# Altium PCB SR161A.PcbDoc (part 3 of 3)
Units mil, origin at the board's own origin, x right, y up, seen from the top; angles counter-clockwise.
Board outline 3150 x 3740 mil, 6 copper layers (Top Layer, Signal Layer 1, Signal Layer 2, Signal Layer 3, Signal Layer 4, Bottom Layer), stack 61.4 mil thick; 187 components, 70 nets, 452 pads, 384 vias.
Unrouted connection lines stored in the file: 5.
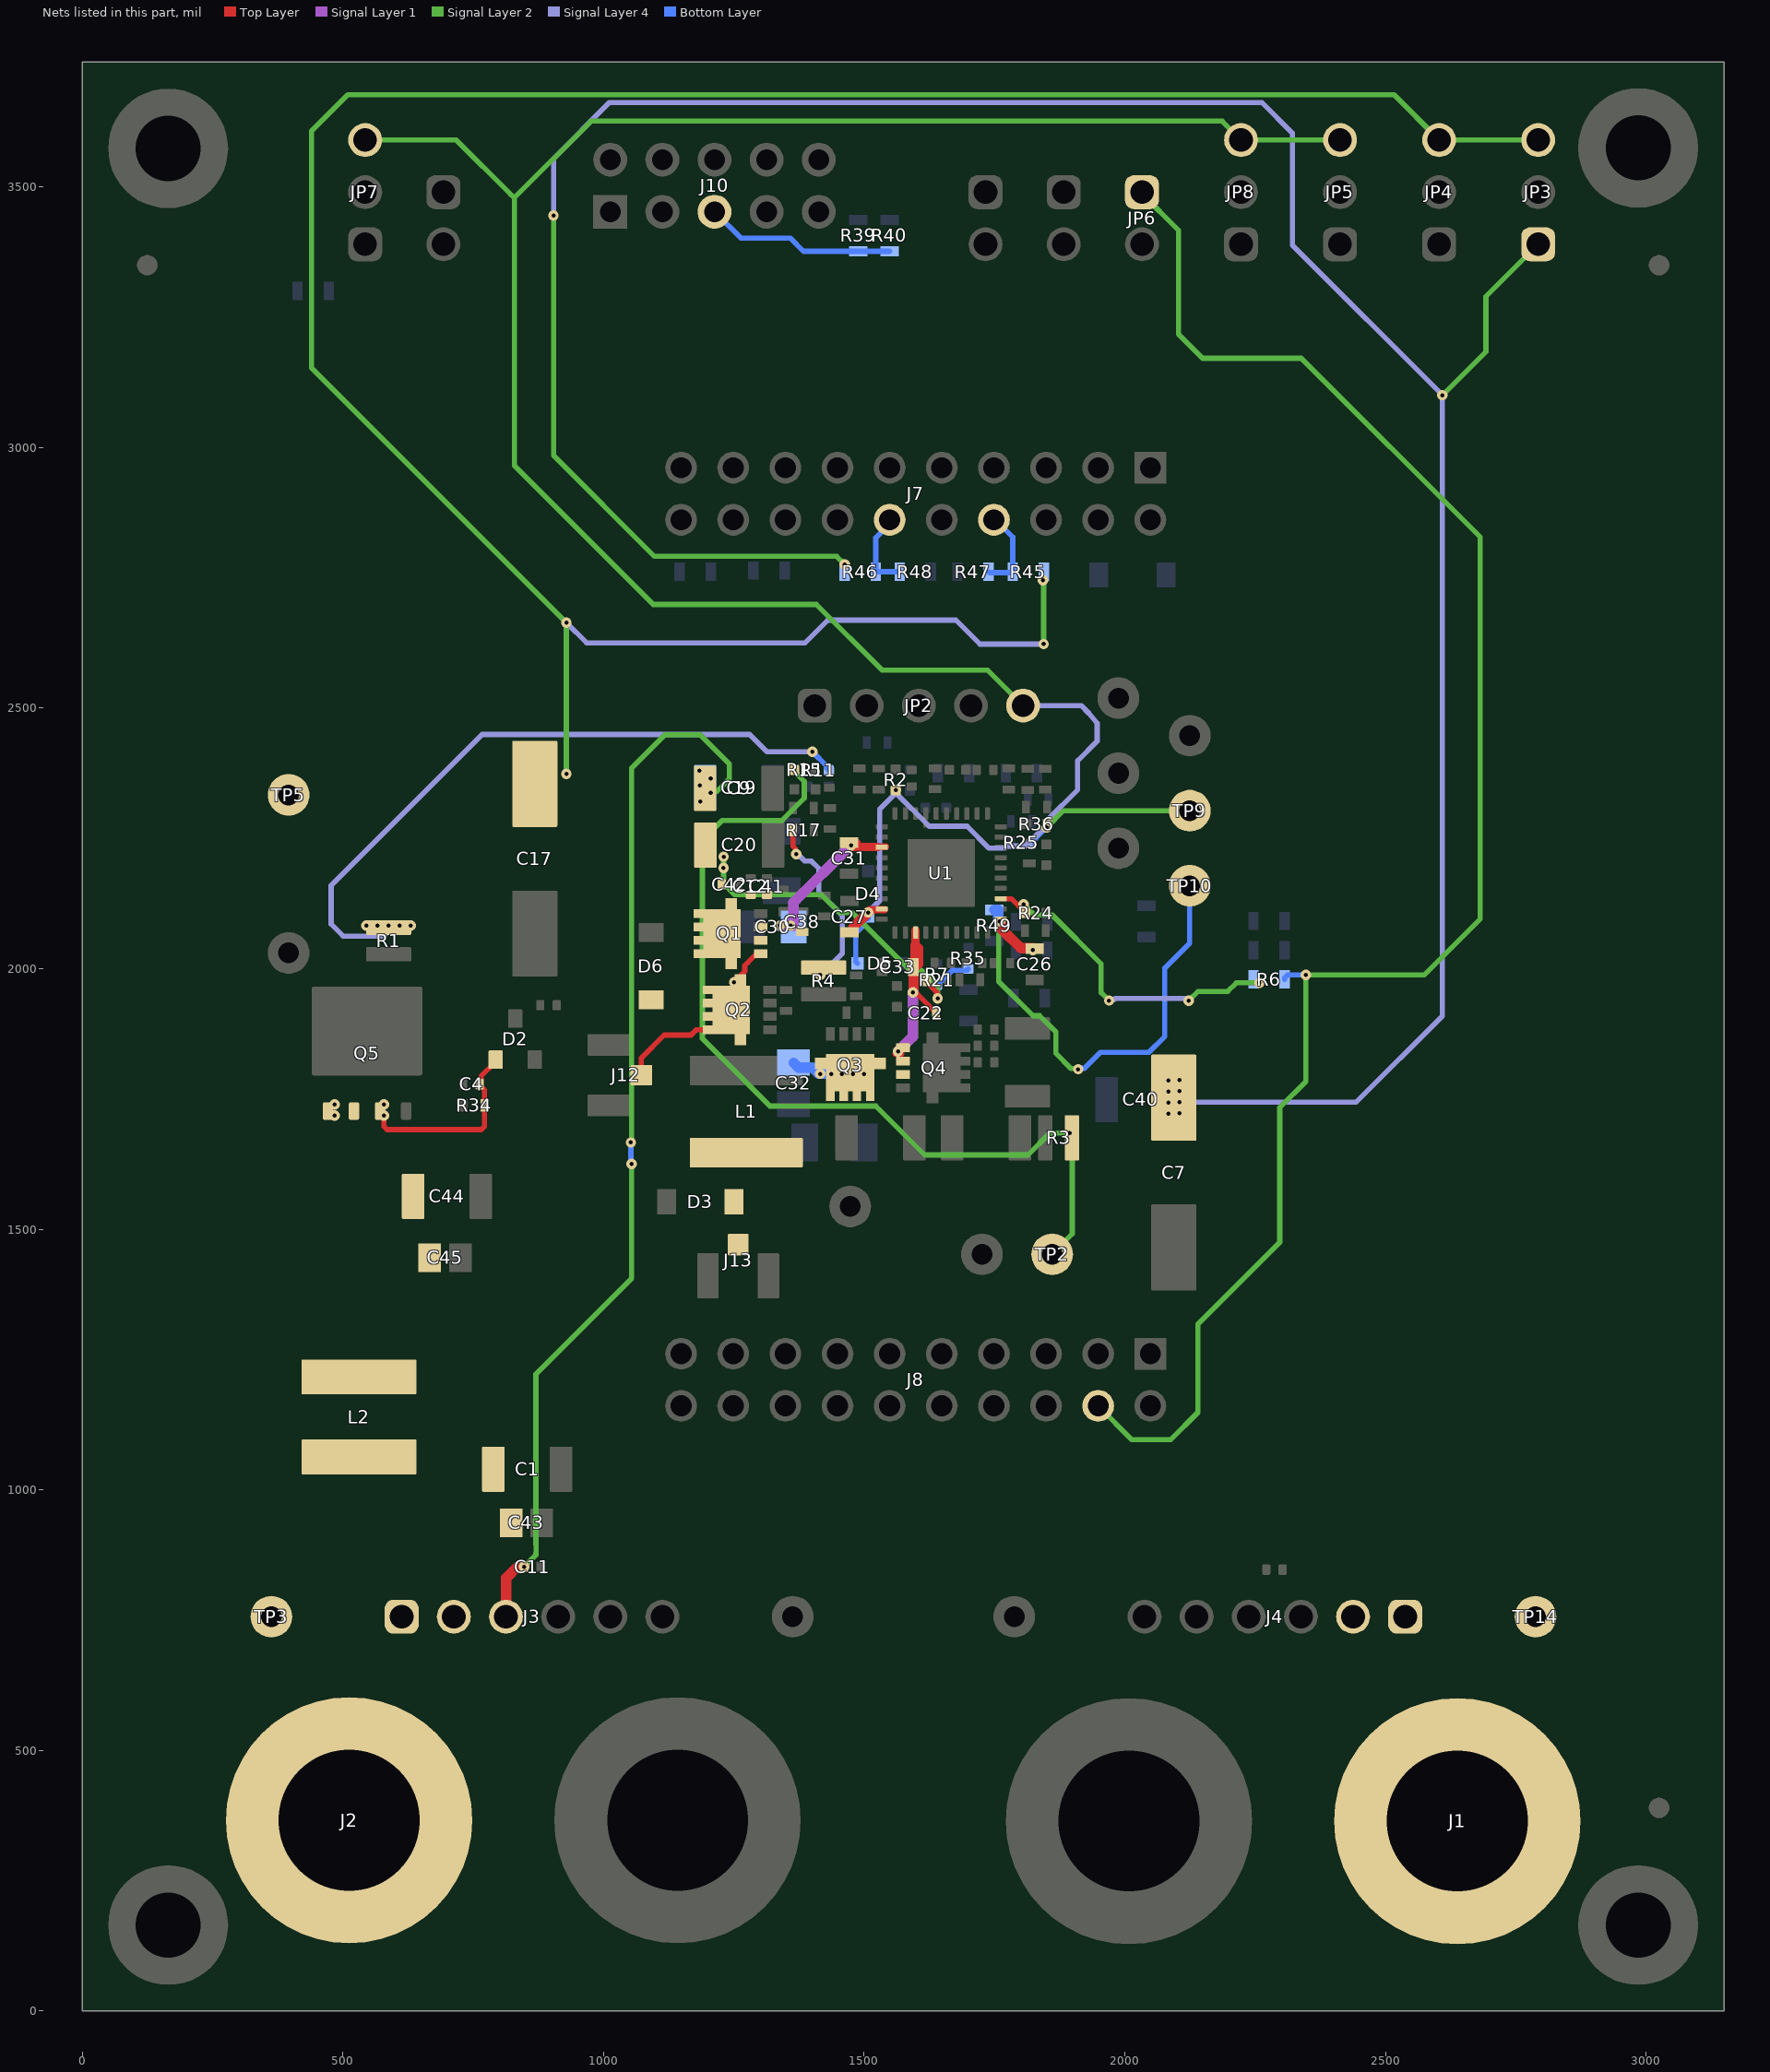
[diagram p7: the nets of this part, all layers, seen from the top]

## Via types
v1: diameter 20, hole 8, Top Layer to Bottom Layer, tented both sides, 366 vias
v2: diameter 19.68, hole 7.87, Top Layer to Bottom Layer, tented both sides, 12 vias
v3: diameter 24, hole 8, Top Layer to Bottom Layer, tented both sides, 6 vias

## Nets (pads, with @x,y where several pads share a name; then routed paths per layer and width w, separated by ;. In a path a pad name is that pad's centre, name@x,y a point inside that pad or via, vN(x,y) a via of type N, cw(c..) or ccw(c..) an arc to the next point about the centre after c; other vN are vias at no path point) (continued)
SW1: C30.2 C31.1 C38.2 D6.1 J12.1 Q1.1 Q1.2 Q1.3 Q2.5-6-7-8 R4.1 R17.2 U1.23 | length 908.5
  Top Layer w10: J12.1@1072.77,1795.91 1072.77,1828.89 1116.62,1872.74 1168.03,1872.74 1178.1,1882.81 Q2.5-6-7-8@1199.75,1882.81 ; Q2.5-6-7-8@1254.49,1979.13 1254.49,1982.31 Q2.5-6-7-8@1254.96,1982.31 ; Q2.5-6-7-8@1264.03,1987.93 1271.1,1995 1271.1,2006.16 1277.6,2012.66 1291.78,2026.83 1298.13,2026.83 Q1.1@1301.4,2030.1 ; R17.2@1363.57,2256 1363.57,2235.17 1367.87,2230.87 1367.87,2222.02 v1(1369.78,2220.1)
  Top Layer w14: U1.23@1530.02,2234.17 U1.23@1540.69,2234.17
  Top Layer w16: C31.1@1474.4,2241.16 1475.96,2239.6 C31.1@1479.84,2239.6 ; C31.1@1476.2,2233.44 U1.23@1526.2,2233.44 ; C31.1@1479.84,2240.29 C31.1@1485.76,2240.29
  Signal Layer 1 w20: v1(1337.85,2082.46) 1364.28,2082.46 1364.28,2126.88 1474.15,2236.75 v1(1475.22,2236.75)
  Signal Layer 4 w10: v1(1369.78,2220.1) 1372.49,2220.1 1385.98,2206.61 1398.72,2206.61 1413.4,2191.93 1413.4,2147.23 1458.24,2102.38 1458.24,2029.26 1416.91,1987.93 v1(1415.58,1987.93)
  Bottom Layer w20: v1(1337.85,2082.46) C30.2@1364.28,2082.46
  other v1: 1250.71,1973.89 1359,2082.46
SW2: C22.1 C32.1 C33.1 D3.1 J13.1 L1.2 Q3.5-6-7-8 Q4.1 Q4.2 Q4.3 U1.33 | length 518.9
  Top Layer w10: Q3.5-6-7-8@1413.06,1814.47 1413.06,1814.96 1418.79,1820.69 Q3.5-6-7-8@1419.28,1820.69 ; Q3.5-6-7-8@1473.44,1800.75 Q3.5-6-7-8@1484.07,1800.75 ; Q4.1@1562.03,1845.35 1562.03,1838.95 1559.57,1836.49 v1@1572.35,1836.49 ; v1(1593.43,1954.59) 1595.34,1952.68 1601.41,1952.68 1635.05,1919.04 C22.1@1635.05,1914.54
  Top Layer w16: U1.33@1598.79,2065.82 U1.33@1598.79,2069.58 U1.33@1598.79,2073.82 ; 1598.83,2052.43 U1.33@1598.83,2065.77
  Top Layer w20: C33.1@1594.47,2003.85 1594.47,1990.89 1594.87,1990.49 v1@1594.87,1960.24 ; C33.1@1594.87,2000.67 1603.78,2009.58 1603.78,2038.42 ; C33.1@1598.58,2005.37 1598.58,2045.37
  Signal Layer 1 w20: v1(1564.98,1841.28) 1593.43,1869.73 v1(1593.43,1954.59)
  Bottom Layer w20: C32.1@1364.78,1819.55 1374.13,1810.2 1401,1810.2 1412.87,1798.32 v1(1436.69,1798.32) v1(1457.8,1798.32) v1(1500.02,1798.32)
  other v1: 1415.58,1798.32 1478.91,1798.32
SYNC: R6.1 R24.1 U1.3 | length 637.3
  Top Layer w10: U1.3@1768.98,2134.46 1782.3,2134.46 1798.34,2118.43 1809.02,2118.43 1809.02,2107.39 R24.1@1809.28,2107.13
  Signal Layer 2 w10: v1(1806.02,2123.81) 1826.55,2103.27 1860.72,2103.27 1954.83,2009.16 1954.83,1954.09 v1(1969.99,1938.93) ; v1(2122.71,1938.79) 2140.54,1956.63 2197.56,1956.63 2213.96,1973.02 v1(2258.41,1973.02)
  Signal Layer 4 w10: v1(1969.99,1938.93) 1971.9,1940.85 1978.97,1940.85 1981.52,1943.39 2115.4,1943.39 2120,1938.79 v1(2122.71,1938.79)
SYNCP: J8.4 JP6.1 R6.2 | length 3361
  Signal Layer 2 w10: J8.4@1949.03,1161.43 1948.81,1161.43 2013.88,1096.35 2087.91,1096.35 2140.32,1148.76 2140.32,1317.92 2297.44,1475.04 2297.44,1733.87 2347.26,1783.69 v1(2347.26,1987.99) 2574.03,1987.99 2682,2095.96 2682,2827.94 2338.5,3171.44 2149.27,3171.44 2102.93,3217.77 2102.93,3417.11 JP6.1@2033.24,3486.8
  Bottom Layer w10: R6.2@2306.88,1979.63 2306.88,1982.99 2311.88,1987.99 v1(2347.26,1987.99)
VBUS: J10.5 R39.2 R40.2 | length 366.1
  Bottom Layer w10: J10.5@1213.82,3451.74 1263.82,3401.74 1358.82,3401.74 1383.82,3376.74 R39.2@1488.82,3376.74 R40.2@1548.82,3376.74
VCC1: C26.2 R49.1 TP10.1 U1.1 | length 979.6
  Top Layer w20: v1@1763.98,2084.74 1763.98,2075.72 1799.15,2040.55 1801.35,2040.55 1802.57,2039.33 C26.2@1824.98,2039.33
  Signal Layer 2 w10: v1@1758.26,2081.47 1758.26,1975.35 1823.83,1909.79 1836.65,1909.79 1868.02,1878.42 1868.02,1837.57 1896.86,1808.73 1909.23,1808.73 v1(1910.72,1807.24) ; v1@1758.27,2081.48 1758.27,2088.55 v1(1760.19,2090.47)
  Bottom Layer w10: v1(1910.72,1807.24) 1912.64,1809.16 1922.71,1809.16 1953.21,1839.66 2046.39,1839.66 2076.94,1870.21 2076.94,2001.58 2124.72,2049.36 TP10.1@2124.72,2159.28
  Bottom Layer w20: R49.1@1749.62,2113.15 1757.12,2113.15 1757.12,2093.53 v1(1760.19,2090.47)
  other v1: 1823.37,2035.91
VCC2: C27.2 D4.2 D5.2 JP2.5 JP5.3 JP7.3 JP8.3 R2.2 R25.2 R36.1 TP9.1 U1.29 | length 5183.4
  Top Layer w14: v1@1510.9,2113.09 U1.29@1538.9,2113.09
  Top Layer w20: C27.2@1479.37,2079.48 v1@1509.62,2109.73
  Signal Layer 2 w10: JP7.3@543,3590.37 717.7,3590.37 821.63,3486.44 829.03,3479.04 ; JP2.5@1804.78,2505.1 1736.72,2573.15 1534.4,2573.15 1408.59,2698.96 1095.7,2698.96 829.03,2965.63 829.03,3479.04 ; v1(1850.25,2270.96) 1882.57,2303.28 TP9.1@2124.72,2303.28 ; JP5.3@2413,3590.37 2223,3590.37 2186.98,3626.39 976.39,3626.39 829.03,3479.04
  Signal Layer 4 w10: v1(1507.82,2107.96) 1507.82,2108.4 1529.93,2130.52 1529.93,2306.12 1560.13,2336.32 v1@1560.13,2338.34 ; v1@1560.13,2343.88 1560.13,2342.68 v1@1560.13,2338.34 ; v1@1561.11,2339.97 v1(1561.11,2342.68) ; JP2.5@1805,2505 1916.43,2505 1931.6,2489.84 1944.74,2473.79 1947,2471.03 1947,2436.62 1909.62,2399.24 1909.62,2343.66 1851.95,2285.99 1851.95,2272.66 v1(1850.25,2270.96) 1847.55,2270.96 1842.55,2265.96 1839.89,2265.96 1809.46,2235.53 1774.19,2235.53 1770.16,2231.51 1739.35,2231.51 1697.44,2273.41 1625.06,2273.41 v1@1560.13,2338.34
  Bottom Layer w10: D5.2@1487.35,2010.13 1483.86,2013.62 1483.86,2068.34 1500.9,2085.38 1500.9,2093.78 1503.45,2096.34 D4.2@1507.42,2096.34 ; R25.2@1822.26,2243.16 1822.26,2246.81 1824.76,2249.31 1828.41,2249.31 v1@1852.34,2273.24
VIN: C1.2 C4.2 C43.1 C44.2 C45.1 D2.1 J2.1 J3.1 J3.2 L2.1 L2.2 Q5.1 Q5.2 Q5.3 R34.2 TP3.1 | length 363.3
  Top Layer w10: v1(579.12,1718.31) 579.12,1697.34 584.98,1691.49 765.71,1691.49 771.96,1697.74 R34.2@771.96,1737.49 771.96,1767.2 762.56,1776.6 C4.2@762.56,1778.57 765.43,1781.44 765.43,1793.77 793.32,1821.66 D2.1@793.32,1825.6
  other v1: 484.07,1718.31 484.07,1739.42 579.12,1739.42
VIN_36: C9.2 C11.1 C12.1 C17.2 C19.2 C20.2 C41.1 C42.1 J3.3 JP3.3 JP4.3 Q1.5-6-7-8 R1.2 R7.2 R11.2 R21.2 R35.2 R45.1 TP5.1 | length 9017.5
  Top Layer w10: R21.2@1620.03,1978.74 1620.03,1974.24 1639.11,1955.16 1639.11,1945.02 v1(1641.02,1943.11)
  Top Layer w20: J3.3@813.61,756.82 813.61,831.13 835.09,852.61 C11.1@847.79,852.61
  Signal Layer 2 w10: v1(847.93,852.61) 870.52,875.21 870.52,878.09 870.71,878.28 870.71,895.68 870.52,895.87 870.52,1222.01 1054.06,1405.55 v1(1054.06,1625.23) v1@1052.57,1626.72 ; v1(928.95,2374.05) v1(928.95,2664.16) 440,3153.11 440,3607.22 509.9,3677.12 2516.25,3677.12 2603,3590.37 JP3.3@2793,3590.37 ; v1(1052.57,1666.75) 1054.06,1668.23 1054.06,2385.2 1118.03,2449.17 1185.08,2449.17 1241.58,2392.67 1241.58,2364.45 1216.33,2339.2 1207.62,2339.2 v1(1205.71,2337.29) ; v1(1230.4,2193.48) 1230.4,2163.57 1251.8,2142.16 1418.03,2142.16 1452.31,2107.88 1476.79,2107.88 1587.45,1997.22 1609.85,1997.22 1641.09,1965.98 v1@1641.09,1939.77 ; v1@1230.55,2197.35 v1(1230.55,2215.07) ; v1(1843.27,2745.31) 1844.44,2744.14 v1(1844.44,2623.02)
  Signal Layer 4 w10: v1(587.95,2082.78) 586.04,2080.87 586.04,2070.74 578.08,2062.79 500.7,2062.79 477.77,2085.71 477.77,2159.75 767.5,2449.48 1280.59,2449.48 1313.72,2416.35 v1(1400.73,2416.35) ; v1(928.95,2664.16) 967.69,2625.42 1386.81,2625.42 1430.38,2668.98 1676.17,2668.98 1722.13,2623.02 v1(1844.44,2623.02)
  Bottom Layer w10: v1@1052.57,1626.72 v1(1052.57,1666.75) ; v1(1400.73,2416.35) 1427.85,2389.22 1427.85,2385.36 R11.2@1432.2,2381.01 ; v1(1641.02,1943.11) 1640.52,1943.6 1640.52,1964.57 1639.07,1966.03 1639.07,1967.1 1669.03,1997.06 1697.23,1997.06 R35.2@1700,1999.82
  other v1: 545.42,2082.78 566.68,2082.78 609.21,2082.78 630.48,2082.78 1185.82,2320.76 1184.66,2352.12 1205.71,2365.29 1184.29,2379.68
VIN_SENSE: J7.8 R45.2 R47.2 | length 159.9
  Bottom Layer w10: R47.2@1738.93,2761.65 1740.59,2759.99 1783.41,2759.99 R45.2@1785.07,2761.65 1785.07,2828.37 1753.05,2860.39 J7.8@1753.05,2860.71
VOUT: C7.2 C40.2 J1.1 J4.1 J4.2 JP3.1 R3.2 R15.2 R46.1 TP2.1 TP14.1 | length 7223.5
  Signal Layer 2 w10: v1@904.19,3445.44 904.19,2985.11 1098.03,2791.27 1447.4,2791.27 v1@1460.03,2778.64 ; v1@1363.81,2381.91 1363.81,2381.01 1385.4,2359.42 1385.4,2327.41 1342.7,2284.71 1335.86,2284.71 1335.73,2284.58 1228.11,2284.58 1189.84,2246.31 1189.84,1866.1 1319.39,1736.55 1522.58,1736.55 1616.41,1642.71 1814.24,1642.71 1856.27,1684.74 v1(1894.08,1684.74) ; TP2.1@1860.73,1452.1 1860.73,1452.81 1899.26,1491.35 1899.26,1676.85 1894.22,1681.88 v1@1894.22,1684.59 ; v1(2609.35,3100.49) 2692.81,3183.95 2692.81,3289.81 JP3.1@2793,3390
  Signal Layer 4 w10: v1@904.19,3445.44 904.19,3554.7 1011.55,3662.07 2263.15,3662.07 2321.81,3603.41 2321.81,3388.03 v1(2609.35,3100.49) 2609.35,1909.57 2444.02,1744.24 v1(2104.62,1744.24) ; JP3.1@2791,3377 2819,3377 JP3.1@2812.69,3370.69
  other v1: 2083.6,1722.35 2104.62,1723.05 2083.6,1743.54 2083.6,1764.73 2104.62,1765.44 2083.6,1785.92 2104.62,1786.63 1365.23,2382.22 1462.83,2775.84 904.19,3445.07
VOUT_SENSE: J7.12 R46.2 R48.2 | length 157.4
  Bottom Layer w10: J7.12@1553.05,2860.71 1553.05,2857.43 1522.51,2826.89 R46.2@1522.51,2761.76 R48.2@1568.34,2761.76
pads on no net: FID1.1 FID2.1 FID3.1 FID4.1 FID5.1 FID6.1 H1.1 H2.1 H3.1 H4.1 J7.5 J7.7 J7.9 J7.11 J7.13 J7.14 J7.15 J7.18 J8.1 J8.5 J8.7 J8.8 J8.9 J8.10 J8.11 J8.12 J8.13 J8.14 J8.15 J8.16 J8.17 J8.18 J8.20 J10.1 J10.2 J10.3 J10.4 J10.7 J10.8 Q5.9@453.13,1805.36 Q5.9@494.18,1816.97 Q5.9@494.18,1862.25 Q5.9@494.18,1907.52 Q5.9@546.54,1816.97 Q5.9@546.54,1862.25 Q5.9@546.54,1867.56 Q5.9@546.54,1907.52 Q5.9@598.9,1816.97 Q5.9@598.9,1862.25 Q5.9@598.9,1907.52 Q5.9@639.95,1805.36 U1.26 U1.34 U1.39

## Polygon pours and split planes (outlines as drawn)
GND on Top Layer "TOP_LAYER_GND_P065" (solid, remove dead copper, pour order 65): 1058.35,1136.55 1126.72,1068.18 1133.39,1063.48 1479.08,1062.75 1549.03,992.8 1549.03,118.68 1652.11,0 3149.61,0 3149.61,3740.16 0,3740.16 0,1833.44 147.48,1636.66 674.41,1636.66 700,1610.34 700,351.19 942.49,108.7 1376.09,108.7 1430,156.26 1430,785.84 1377.14,854.13 1054.91,854.13 956.87,944.16 956.43,1173.43 856.03,1259.28 856.13,1593.55 881.85,1623.76 1058.35,1623.76
VIN on Top Layer "TOP_LAYER_VIN_P026" (solid, remove dead copper, pour order 26): 370,1770 350,1750 350,1255.42 419.39,1186.03 422.37,1110.21 650,1109.77 650,1183.02 690,1220.86 690,1750 670,1770
SW2 on Top Layer "TOP_LAYER_SW2_P053" (solid, pour order 53): 1563.31,1863.3 1583.11,1863.3 1587.79,1858.61 1587.79,1748.69 1571.59,1732.49 1443.88,1732.49 1431.35,1719.47 1431.35,1657.71 1337.94,1564.3 1337.94,1469.3 1311.81,1443.16 1196.84,1443.16 1170,1470 1170,1726.96 1178,1734.96 1339.18,1734.96 1344.24,1740.02 1364.22,1760 1389.57,1760 1405.35,1775.78 1405.35,1831.97 1418.17,1844.79 1544.87,1844.85
NetL1_1 on Top Layer "TOP_LAYER_NETL1_1_P054" (solid, remove dead copper, pour order 54): 1342.24,1845.75 1122.08,1845.75 1118.43,1842.1 1118.43,1751.47 1122.69,1747.22 1329.49,1747.22 1352.27,1770 1383.61,1770 1394.94,1781.33 1394.94,1835.97 1413.69,1854.73 1413.69,1896.5 1455.75,1938.56 1455.75,1964.77 1369.09,1964.76 1369.09,1891.04 1351.05,1873 1351.05,1854.56
Q4_D on Top Layer "TOP_LAYER_Q4_D_P052" (solid, pour order 52): 1615.05,1927.29 1699.23,1927.29 1727.98,1898.54 1727.98,1806.8 1740.03,1794.75 1863.67,1794.75 1880,1778.43 1880,1623.76 1868.42,1612.18 1763.3,1612.16 1757.09,1618.37 1757.09,1671.65 1740.65,1688.64 1638.22,1688.64 1618.3,1666.57 1618.3,1627.47 1616.17,1625.34 1576.35,1625.19 1564.88,1636.66 1564.88,1716.41 1570.51,1722.05 1579,1722.05 1605.76,1748.81 1606.51,1918.75
VIN_36 on Top Layer "TOP_LAYER_VIN_36_P046" (solid, remove dead copper, pour order 46): 379.39,2059.37 673.91,2059.37 803.33,2188.79 1118.27,2188.78 1131.1,2175.95 1131.11,2016.04 1146.55,2000.59 1255.99,2000.61 1255.99,2073.01 1280.45,2097.47 1280.45,2115.99 1303.41,2139.03 1323.52,2139.03 1323.52,2151.92 1244.52,2151.92 1240.07,2156.37 1240.07,2373.31 1209.78,2403.6 400.95,2403.6 348.98,2351.63 348.98,2089.78
SW1 on Top Layer "TOP_LAYER_SW1_P043" (solid, remove dead copper, pour order 43): 1459.2,2014.18 1459.2,1986.65 1450.75,1978.2 1314.64,1978.2 1280.64,1942 1280.64,1860.52 1273.51,1853.39 1086.56,1853.39 1057.46,1882.49 1057.46,1978.27 1067.03,1987.93 1245.68,1987.93 1278.18,2020.42 1278.16,2078.37 1294.07,2094.28 1379.1,2094.28
VOUT on Top Layer "Top Layer-VOUT" (solid, remove dead copper, pour order 32): 2140.07,1558.51 2329.46,1369.11 2329.46,-9 3147.2,-9 3144.78,1871.28 3112.26,1903.8 2057.93,1903.8 1880,1725.87 1880,1558.51
AGND on Top Layer "TOP_LAYER_AGND_P031" (solid, remove dead copper, pour order 31): 3149.61,3740.16 3149.61,1942.09 3118.18,1910.66 2054.8,1910.66 1922.48,1777.09 1894.08,1777.09 1870.13,1801.04 1870.13,1900.82 1856.78,1914.17 1665.46,1914.17 1612.47,1967.16 1612.47,1967.96 1613.01,1968.51 1613.01,2052.23 1613.58,2052.8 1613.58,2079.08 1604.22,2088.44 1602.95,2088.44 1599.54,2091.85 1561.68,2091.85 1554.02,2099.5 1554.02,2101.63 1558.02,2105.63 1558.02,2275.39 1537.81,2295.6 1469.7,2295.6 1435.95,2329.36 1356.2,2329.36 1356.2,2442.24 1356.2,2637.18 1287.55,2705.83 0,2705.83 0,3740.16
NetQ5_5 on Top Layer "TOP_LAYER_NETQ5_5_P030" (solid, remove dead copper, pour order 30): 200,1809.29 200.81,1809.29 235.1,1777.25 667.25,1777.25 700,1810 700,2010 663.2,2046.8 230.81,2046.8 200,2015.98
VIN on Top Layer "TOP_LAYER_VIN_P007" (solid, remove dead copper, pour order 7): 220,1015.79 220,280 391.3,108.7 789.22,108.7 843.5,162.98 843.5,1095.98 818.11,1121.37 324.79,1120.58
AGND on Signal Layer 3 "SIGNAL_LAYER_3_AGND_P068" (solid, remove dead copper, pour order 68): 1060,1127.59 1060,1580.86 1000.37,1642.19 143.37,1642.19 0,1833.48 0,3740.16 3149.61,3740.16 3149.61,0 1652.11,0 1550,117.57 1550,1026.16 1513.39,1062.77 1135.05,1062.77
AGND on Signal Layer 4 "SIGNAL_LAYER_4_AGND_P069" (solid, remove dead copper, pour order 69): 1060,1127.59 1060,1592.77 1011.95,1642.19 135.28,1642.19 0,1822.69 0,3740.16 3149.61,3740.16 3149.61,0 1646.85,0 1540,123.03 1540,1009.26 1486.49,1062.77 1135.05,1062.77
NetQ5_5 on Bottom Layer "BOTTOM_LAYER_NETQ5_5_P070" (solid, remove dead copper, pour order 70): 200,1809.29 200.81,1809.29 235.1,1777.25 667.25,1777.25 700,1810 700,2010 663.2,2046.8 230.81,2046.8 200,2015.98
GND on Bottom Layer "BOTTOM_LAYER_GND_P072" (solid, remove dead copper, pour order 72): 1060,1127.59 1060,1580.29 1003.13,1638.78 133.57,1638.78 0,1817 0,3740.16 3149.61,3740.16 3149.61,0 1652.11,0 1549.03,118.68 1549.03,992.22 1478.49,1062.77 1135.05,1062.77
AGND on Signal Layer 2 "SIGNAL_LAYER_2_AGND_P067" (solid, remove dead copper, pour order 67): 1060,1122.26 1060,1592.77 1015.26,1638.78 150.99,1638.78 0,1840.24 0,3740.16 3149.61,3740.16 3149.61,0 1643.42,0 1549.03,108.68 1549.03,999.74 1486,1062.77 1128.89,1062.77
GND on Signal Layer 1 "SIGNAL_LAYER_1_GND_P066" (solid, remove dead copper, pour order 66): 148.44,1642.19 0,1840.24 0,3740.16 3149.61,3740.16 3149.61,0 1653.42,0 1550,119.08 1550,997.2 1484.43,1062.77 1135.05,1062.77 1062.48,1120 1062.48,1599.63 1011.23,1642.19

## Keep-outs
Keep-Out Layer:
  text ".Layer_Name" at 577,-858.49 h60

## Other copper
Top Layer:
  pour cut-out: 1004.14,1641.69 ccw(c1027.14,1641.69) 1027.14,1618.69 ccw(c1027.14,1641.69) 1050.14,1641.69 ccw(c1027.14,1641.69) 1027.14,1664.69 ccw(c1027.14,1641.69)
  pour cut-out: 869.6,756.62 ccw(c913.17,756.62) 913.17,713.05 ccw(c913.17,756.62) 956.73,756.62 ccw(c913.17,756.62) 913.17,800.18 ccw(c913.17,756.62)
  pour cut-out: 2195.11,757.23 ccw(c2238.68,757.23) 2238.68,713.66 ccw(c2238.68,757.23) 2282.24,757.23 ccw(c2238.68,757.23) 2238.68,800.8 ccw(c2238.68,757.23)
  pour cut-out: 2288.67,866.9 2247.38,866.98 2214.3,833.9 2214.3,782.02 2260.71,782.02 2260.71,817.27 2271.02,827.59 2288.67,827.59
  pour cut-out: 862.94,872.67 904.23,872.75 937.31,839.67 937.31,787.79 890.9,787.79 890.9,823.04 880.59,833.36 862.94,833.36
  pour cut-out: 1585.46,2406.27 1626.21,2406.27 1626.21,2370 1585.46,2370
  pour cut-out: 1503,1989.99 1522.55,1989.99 1522.55,1976.75 1503.01,1976.75
  text ".Layer_Name" at 577,-858.49 h60
Signal Layer 1:
  pour cut-out: 1005.37,1641.44 ccw(c1028.37,1641.44) 1028.37,1618.44 ccw(c1028.37,1641.44) 1051.37,1641.44 ccw(c1028.37,1641.44) 1028.37,1664.44 ccw(c1028.37,1641.44)
  pour cut-out: 1005.37,1602.23 ccw(c1028.37,1602.23) 1028.37,1579.23 ccw(c1028.37,1602.23) 1051.37,1602.23 ccw(c1028.37,1602.23) 1028.37,1625.23 ccw(c1028.37,1602.23)
  pour cut-out: 2249.19,846.85 ccw(c2272.19,846.85) 2272.19,823.85 ccw(c2272.19,846.85) 2295.19,846.85 ccw(c2272.19,846.85) 2272.19,869.85 ccw(c2272.19,846.85)
  pour cut-out: 869.6,756.62 ccw(c913.17,756.62) 913.17,713.05 ccw(c913.17,756.62) 956.73,756.62 ccw(c913.17,756.62) 913.17,800.18 ccw(c913.17,756.62)
  pour cut-out: 2194.6,757.09 ccw(c2238.16,757.09) 2238.16,713.53 ccw(c2238.16,757.09) 2281.73,757.09 ccw(c2238.16,757.09) 2238.16,800.66 ccw(c2238.16,757.09)
  pour cut-out: 662.93,1177.97 393.44,1177.97 393.44,1100 662.93,1100
  text ".Layer_Name" at 577,-858.49 h60
Signal Layer 2:
  text ".Layer_Name" at 577,-858.49 h60
Signal Layer 3:
  text ".Layer_Name" at 577,-858.49 h60
Signal Layer 4:
  text ".Layer_Name" at 577,-858.49 h60
Bottom Layer:
  pour cut-out: 1011.25,1644.93 ccw(c1034.25,1644.93) 1034.25,1621.93 ccw(c1034.25,1644.93) 1057.25,1644.93 ccw(c1034.25,1644.93) 1034.25,1667.93 ccw(c1034.25,1644.93)
  pour cut-out: 1007.23,1603.52 ccw(c1030.23,1603.52) 1030.23,1580.52 ccw(c1030.23,1603.52) 1053.23,1603.52 ccw(c1030.23,1603.52) 1030.23,1626.52 ccw(c1030.23,1603.52)
  pour cut-out: 2249.19,846.85 ccw(c2272.19,846.85) 2272.19,823.85 ccw(c2272.19,846.85) 2295.19,846.85 ccw(c2272.19,846.85) 2272.19,869.85 ccw(c2272.19,846.85)
  pour cut-out: 869.6,756.62 ccw(c913.17,756.62) 913.17,713.05 ccw(c913.17,756.62) 956.73,756.62 ccw(c913.17,756.62) 913.17,800.18 ccw(c913.17,756.62)
  pour cut-out: 2194.94,757.52 ccw(c2238.5,757.52) 2238.5,713.96 ccw(c2238.5,757.52) 2282.07,757.52 ccw(c2238.5,757.52) 2238.5,801.09 ccw(c2238.5,757.52)
  pour cut-out: 865.41,776.26 865.41,737.38 860.04,737.38 860.04,776.25
  text ".Layer_Name" at 577,-858.49 h60

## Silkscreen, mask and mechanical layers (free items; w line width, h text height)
Top Overlay:
  lines w6: 180,1170 357.3,1170 380.91,1146.39 ; 1888.16,2212.4 1927.68,2187.78 ; 1927.42,2102.88 1927.42,2187.88 ; 1927.68,2167.92 2000.38,2167.92
  lines w10: 411.12,1120 653.06,1120.35 ; 411.12,1165 653.06,1165.35 ; 543,3340.51 543,3310.84 544.21,3309.63 1110.7,3309.63 ; 693,3309.63 693,3340.51 ; 1316.6,3309.63 2603,3309.63 2603,3340.51 ; 1733,3309.63 1733,3340.51 ; 1883,3309.63 1883,3340.51 ; 2033,3309.63 2033,3340.51 ; 2223,3309.63 2223,3340.51 ; 2413,3309.63 2413,3340.51 ; -0.02,0.05 3149.58,0.05 3149.58,3740.2 -0.02,3740.2 -0.02,0.05 ; 1155.71,1608.68 1871.57,1608.68 1871.57,2402.68 1155.71,2402.68 1155.71,1608.68
  text "VIN" at 2531.94,3564.7 h30 r90
  text "VIN" at 2722.43,3564.7 h30 r90
  text "VCC2" at 2154,3540.84 h30 r90
  text "FPWM" at 2344,3540.84 h30 r90
  text "VCC2" at 478.08,3535.4 h30 r90
  text "PSM" at 2344,3364.28 h30 r90
  text "AGND" at 477.47,3353.77 h30 r90
  text "AGND" at 2154,3353.77 h30 r90
  text "AGND" at 2531.94,3353.77 h30 r90
  text "VOUT" at 2722.43,3339.03 h30 r90
  text "AGND" at 1161.16,3297.21 h30
  text "CDC" at 1748,3193.66 h30 r90
  text "BIAS" at 2807.99,3178.66 h30 r90
  text "DRV1" at 708,3173.66 h30 r90
  text "DTRK" at 1898,3163.67 h30 r90
  text "SYNC" at 2048,3163.67 h30 r90
  text "ADDR" at 2237.99,3163.67 h30 r90
  text "MODE" at 2423.4,3163.67 h30 r90
  text "EN/UVLO" at 2617.99,3073.69 h30 r90
  text "ILIMCOMP" at 557.99,3053.7 h30 r90
  text "J7" at 2165.51,2895.67 h30
  text "'.PRJ_Title'" at 310.46,2722.27 h60
  text ".PRJ_Number" at 308.46,2638.25 h40
  text "REV. .PCB_Rev" at 308.46,2556.44 h40
  text "SOLUTION SIZE:" at 614.73,2539.09 h60
  text "GND" at 2384.11,2506.51 h30
  text "18 mm x 20 mm" at 615.82,2462.95 h60
  text "GND" at 2443.84,2434.81 h30
  text "BODE" at 1396.23,2417.27 h30
  text "AGND" at 1546.46,2417.27 h30
  text "FB" at 1687.2,2417.27 h30
  text "VCC2" at 1760.87,2417.27 h30
  text "COMP" at 2384.11,2354.95 h30
  text "VCC2" at 2443.84,2284.53 h30
  text "SS/ATRK" at 2384.11,2207.97 h30
  text "VCC1" at 2443.84,2135.84 h30
  text "nRST" at 1376.21,1396.05 h30
  text "J8" at 2133.28,1190.95 h30
  text "CUT HERE" at 173.98,1183.43 h40
  text "VIN" at 130.5,731.83 h50
  text "GND" at 1504.18,731.83 h50
  text "VOUT" at 2889.72,731.83 h50
  text "S+" at 827.24,623.77 h30 r90
  text "S-" at 927.85,623.77 h30 r90
  text "S-" at 2252.24,623.78 h30 r90
  text "S+" at 2352.85,623.78 h30 r90
  text "9-36V" at 757,115.08 h40
  text "5-32V" at 2238.38,115.08 h40
  text "VIN" at 439.34,52.75 h50
  text "GND" at 1100.03,52.75 h50
  text "GND" at 1892.26,52.75 h50
  text "VOUT" at 2639.73,52.75 h50
  text "Max.: 6.2A" at 650.35,36.26 h40
  text "Max.: 3A /50W" at 2080.01,36.26 h40
  text ".Layer_Name" at 577,-858.49 h60
Bottom Overlay:
  lines w10: 1162.91,1615.4 1871.57,1615.4 1871.57,2402.8 1162.91,2402.8 1162.91,1615.4
  text ".Layer_Name" at 577,-858.49 h60
Top Paste:
  text ".Layer_Name" at 577,-858.49 h60
Bottom Paste:
  text ".Layer_Name" at 577,-858.49 h60
Top Solder:
  rectangle: 370,1756.38 437.13,1791.96
  text ".Layer_Name" at 577,-858.49 h60
  text ".Layer_Name" at 577,-858.49 h60
Bottom Solder:
  text ".Layer_Name" at 577,-858.49 h60
Drill Guide:
  text ".Layer_Name" at 577,-858.49 h60
M1 Board Outline:
  the board outline again, w10
  text ".Layer_Name" at 577,-858.49 h60
M2 Board Dimensions:
  rectangle: 0,-275 125,-150
  rectangle: 125,-400 500,-275
  lines w7: 0,-275 1000,-275 ; 125,-400 125,-150 ; 250,-400 250,-150 ; 500,-400 500,-150 ; 750,-400 750,-150 ; 0,-400 1000,-400 1000,-150 0,-150 0,-400
  text ".Layer_Name" at 577,-858.49 h60
M3 3D STEP Top:
  text ".Layer_Name" at 577,-858.49 h60
M4 3D STEP Bottom:
  text ".Layer_Name" at 577,-858.49 h60
M5 Assembly Top:
  lines w10: -292,-930.17 6308,-930.17 ; -292,-726.83 6310,-726.83 ; -292,-523.5 -292,-1133.5 3713,-1133.5 6310,-1133.5 6310,-523.5 -291.5,-523.5 -291.5,-1133.5 1284,-1133.5 ; 2173,-1133.5 2173,-523.5 ; 3440,-726.83 3440,-523.5 ; 4280,-726.83 4280,-523.5 ; 4902,-1140 4902,-937.17
  text "COMPONENTS MARKED 'DNP' SHOULD NOT BE POPULATED." at 1153.5,-318.5 h60
  text "ASSEMBLY VARIANT:" at 1153,-434 h60
  text ".VariantName" at 2189,-434 h60
  text "PCB VIEWED FROM TOP SIDE" at -228.5,-655.67 h60
  text "BOARD #:" at 2248,-655.67 h60
  text ".PRJ_Number" at 2793.5,-655.67 h60
  text "REV:" at 3638,-655.67 h60
  text ".PCB_Rev" at 3929.5,-655.67 h60
  text "SVN REV:" at 4476,-655.67 h60
  text ".VersionControl_RevNumber" at 4982,-655.67 h60
  text "TID #:" at 2248,-859 h60
  text ".TID" at 2793.5,-859 h60
  text "PLOT NAME =" at -228.5,-1064.34 h60
  text ".plot_File_Name" at 577,-1064.34 h60
  text "GENERATED    :" at 2250,-1064.34 h60
  text ".Print_Date" at 3119.5,-1064.34 h60
  text ".Print_Time" at 3848.5,-1064.34 h60
  text "TEXAS INSTRUMENTS" at 5113,-1064.34 h60
M6 Assembly Bottom:
  lines w10: -292.5,-727.33 6309.5,-727.33 ; -290.5,-930.67 6309.5,-930.67 ; 1115.5,-1140.5 1115.5,-937.67 ; 1737.5,-727.33 1737.5,-524 ; 2577.5,-727.33 2577.5,-524 ; 3844.5,-1134 3844.5,-524 ; 4733.5,-1134 6309,-1134 6309,-524 -292.5,-524 -292.5,-1134 2304.5,-1134 6309.5,-1134 6309.5,-524
  text "COMPONENTS MARKED 'DNP' SHOULD NOT BE POPULATED." at 6102,-318 h60
  text ".VariantName" at 5058,-434 h60
  text "ASSEMBLY VARIANT:" at 6097,-434 h60
  text ".VersionControl_RevNumber" at 1035.5,-656.17 h60
  text "SVN REV:" at 1541.5,-656.17 h60
  text ".PCB_Rev" at 2088,-656.17 h60
  text "REV:" at 2379.5,-656.17 h60
  text ".PRJ_Number" at 3224,-656.17 h60
  text "BOARD #:" at 3769.5,-656.17 h60
  text "PCB VIEWED FROM BOTTOM SIDE" at 6246,-656.17 h60
  text ".TID" at 3224,-859.5 h60
  text "TID #:" at 3769.5,-859.5 h60
  text "TEXAS INSTRUMENTS" at 904.5,-1064.84 h60
  text ".Print_Time" at 2169,-1064.84 h60
  text ".Print_Date" at 2898,-1064.84 h60
  text "GENERATED    :" at 3767.5,-1064.84 h60
  text ".plot_File_Name" at 5440.5,-1064.84 h60
  text "PLOT NAME =" at 6246,-1064.84 h60
M9 Title Sheet:
  drawing of 57 lines, arcs and shapes, not listed
  text "1" at 739.84,8036.5 h70
  text "2" at 3235.5,8036.5 h70
  text "3" at 5724.84,8036.5 h70
  text "4" at 8231.51,8036.5 h70
  text "5" at 10730.5,8036.5 h70
  text "6" at 13235.5,8036.5 h70
  text "A" at -416.5,6893.5 h70
  text "A" at 14383.5,6893.5 h70
  text "B" at -416.5,4513.5 h70
  text "B" at 14383.5,4513.5 h70
  text "C" at -416.5,2138.5 h70
  text "C" at 14383.5,2138.5 h70
  text "PROJECT TITLE:" at 11343.5,277.5 h45
  text ".PRJ_Title" at 11393.5,144.17 h70
  text "DESIGNED FOR:" at 11343.5,-23.5 h45
  text ".PRJ_Customer" at 11393.5,-163.5 h70
  text "D" at -416.5,-231.5 h70
  text "D" at 14383.5,-231.5 h70
  text "FILE NAME:" at 11343.5,-323.5 h45
  text ".PCB_File_Name_No_Path" at 11393.5,-443.5 h70
  text "Texas Instruments (TI) and/or its licensors do not warrant the accuracy or completeness of this specification" at 6374,-605.34 h45
  text "ENGINEER:" at 11343.5,-613.5 h45
  text "LAYOUT BY:" at 12848.5,-613.5 h45
  text "or any information contained therein. TI and/or its licensors do not warrant that this design will meet" at 6329.01,-718 h45
  text ".PRJ_Engineer" at 11393.5,-768.49 h70
  text ".PCB_Layout" at 12899,-768.49 h70
  text "the specifications, will be suitable for your application or fit for any particular purpose, or will operate in" at 6329.01,-830.67 h45
  text ".Layer_Name" at 577,-858.49 h60
  text "ALTIUM DESIGNER VERSION:" at 12848.5,-923.5 h45
  text "an implementation. TI and/or its licensors do not warrant that the design is production worthy. You should" at 6329.01,-943.33 h45
  text "completely validate and test your design implementation to confirm the system functionality for your application." at 6374,-1056 h45
  text ".print_Scale" at 11393.5,-1056.83 h70
  text ".Application_BuildNumber" at 12899,-1056.83 h70
  text "1" at 739.84,-1263.5 h70
  text "2" at 3235.5,-1263.5 h70
  text "3" at 5724.84,-1263.5 h70
  text "4" at 8231.51,-1263.5 h70
  text "5" at 10730.5,-1263.5 h70
  text "6" at 13235.5,-1263.5 h70
M10 Fab Notes:
  drawing of 189 lines, arcs and shapes, not listed
  text "DESIGN INFORMATION" at 12382.02,6356.17 h60
  text "MIN. TRACK WIDTH:" at 11737.46,6224.05 h60
  text "8" at 12833.7,6224.05 h60
  text "MIL" at 12988.46,6224.05 h60
  text "6" at 12840,6120 h60
  text "MIN. CLEARANCE:" at 11737.46,6099.92 h60
  text "MIL" at 12988.46,6099.92 h60
  text "19.685" at 12621.93,5986.67 h60
  text "MIN. VIA PAD SIZE:" at 11737.46,5975.8 h60
  text "MIL" at 12988.46,5975.8 h60
  text "0.05mm (2MIL)" at 12432.46,5845.9 h60
  text "MINIMUM ANNULAR RING" at 11408.23,5837.67 h60
  text "EXTERNAL" at 13140.46,5837.67 h60
  text "PER" at 11608.23,5727.55 h60
  text "IPC-D-275 CLASS 2 LEVEL C" at 11828.23,5727.54 h60
  text "MIL, HOLES" at 13316.46,5627.07 h60
  text "+/-" at 12924,5618.48 h60
  text "+/-" at 13778,5618.48 h60
  text "REGISTRATION TOLERANCES:" at 11408.23,5617.42 h60
  text "METAL" at 12608,5617.42 h60
  text "5" at 13184.2,5617.42 h60
  text "3" at 14017.2,5617.42 h60
  text "MIL" at 14133.46,5617.42 h60
  text "HOLE SIZE TOLERANCE (UNLESS OTHERWISE SPECIFIED):" at 11408.23,5519.1 h60
  text "+/-" at 13778,5516.23 h60
  text "3" at 14017.2,5515.17 h60
  text "MIL" at 14133.46,5515.17 h60
  text "MATERIAL:" at 11333.46,5377.52 h60
  text "FR-4 High Tg" at 12319.9,5249 h60
  text "X" at 12175.46,5241.01 h60
  text "FR-4" at 11754.46,5236.49 h60
  text "OTHER" at 13242.46,5236.49 h60
  text "62 MIL (1.6mm) +/-10%" at 12074.56,5093.46 h60
  text "X" at 11954.46,5091.01 h60
  text "THICKNESS:" at 11408.23,5085.24 h60
  text "OTHER" at 13359.46,5085.24 h60
  text "TOLERANCE:" at 11408.23,4946.92 h60
  text "X" at 12256.46,4946.92 h60
  text "ANSI IPC-6012 TYPE 3 CLASS 2" at 12434.48,4946.92 h60
  text "OTHER +/-" at 12434.46,4802.73 h60
  text "BOW & TWIST:" at 11408.23,4657.54 h60
  text "X" at 12256.46,4657.54 h60
  text "ANSI IPC-6012 TYPE 3 CLASS 2" at 12434.48,4657.54 h60
  text "OTHER +/-" at 12434.46,4510.85 h60
  text "DRILLING:" at 11333.46,4380.23 h60
  text "NC_DRILL FILES" at 13094.46,4275.04 h60
  text "REFERENCE:" at 11408.23,4271.1 h60
  text "X" at 12065.46,4271.01 h60
  text "AS SHOWN" at 12243.46,4271.1 h60
  text "X" at 12966.46,4271.1 h60
  text "OTHER" at 13392.46,4128.85 h60
  text "PTH COPPER THICKNESS:" at 11407.91,4125.32 h60
  text "X" at 12547.14,4125.32 h60
  text "20-30 um" at 12675.14,4125.32 h60
  text "BOARD FINISH:" at 11333.46,3977.73 h60
  text "SILKSCREEN:" at 11488.68,3867.6 h60
  text "X" at 12446.46,3867.6 h60
  text "TOP" at 12563.46,3867.6 h60
  text "X" at 12956.46,3867.6 h60
  text "BOTTOM" at 13074.46,3867.6 h60
  text "SILKSCREEN COLOR:" at 11488.68,3712.41 h60
  text "X" at 12445.46,3712.41 h60
  text "WHITE" at 12563.46,3712.41 h60
  text "OTHER" at 13074.46,3712.41 h60
  text "X" at 12576.46,3568.96 h60
  text "GREEN" at 12694.46,3568.96 h60
  text "OTHER" at 13312.46,3568.96 h60
  text "SOLDER RESIST COLOR:" at 11488.68,3562.1 h60
  text "MATTE" at 12694.46,3414.71 h60
  text "SEMI-GLOSS" at 13312,3414.07 h60
  text "IMMERSION GOLD (ENIG)" at 12394.46,3241.94 h60
  text "ENEPIG" at 13732,3234.72 h60
  text "SURFACE FINISH:" at 11333.46,3233.72 h60
  text "X" at 12216.46,3233.72 h60
  text "IMM. TIN/SILVER OR EQUIV" at 11663,3096.4 h60
  text "OTHER" at 13094.46,3092.47 h60
  text "ARRAY/PANEL:" at 11333.46,2937.09 h60
  text "CUT AND TRIM PER M1 BOARD OUTLINE" at 12394.46,2928.87 h60
  text "N.C. ROUTE" at 12394.46,2792.9 h60
  text "X" at 13082.46,2792.9 h60
  text "V. SCORE" at 13260.46,2792.9 h60
  text "CERTIFICATION:" at 11333.46,2663.77 h60
  text "MATERIALS AND WORKMANSHIP FOR ALL PCBS" at 12058.46,2663.77 h60
  text "TO MEET OR EXCEED THE REQUIREMENTS OF:" at 12058.46,2569.71 h60
  text "X" at 11695.97,2441.08 h60
  text "ANSI IPC-A-600F CLASS ->" at 11823.96,2441.08 h60
  text "X" at 13471.97,2441.08 h60
  text "2" at 13581.96,2441.08 h60
  text "1" at 13266.96,2439.58 h60
  text "3" at 13935.96,2439.58 h60
  text "X" at 12507.97,2293.39 h60
  text "RoHS" at 12635.96,2293.39 h60
  text "OTHER" at 13280.36,2293.39 h60
  text "PER ORDER" at 13677.42,2293.39 h60
  text "ALL BOARDS MUST MEET OR EXCEED UL94-V0 REQUIREMENTS." at 11361,2139.57 h60
  text "PCB MUST BEAR THE UL94V-0 UL REGISTERED MATERIAL ID NUMBER" at 11361,2023.5 h60
  text "ADDITIONAL REQUIREMENTS:" at 11333.46,1854.08 h60
  text "MICROSECTION:" at 11408.23,1746.95 h60
  text "YES" at 12313.96,1746.95 h60
  text "REQUIRED" at 13175.46,1602.62 h60
  text "BARE BOARD ELEC. TEST:" at 11408.23,1599.76 h60
  text "NONE" at 12713.96,1599.76 h60
  text "X" at 13057.46,1599.76 h60
  text "PER ORDER" at 13767.46,1599.76 h60
  text "X" at 11470,1443.39 h60
  text "VIAS REQUIRE NON-CONDUCTIVE FILL AND PLANARIZE" at 11576.38,1394.82 h59
  text "XX MIL VIAS REQUIRE CONDUCTIVE FILL AND PLANARIZE" at 11584.38,1290.84 h60
  text "OUTER XX MIL TRACES REQUIRE 50 OHM SINGLE-ENDED IMPEDANCE" at 11583.39,1127.46 h58
  text "LAYER 2 & 3 (INNER LAYERS) XX MIL WIDE, XX MIL SPACE / TRACES REQUIRE 100 OHM DIFFERENTIAL IMPEDANCE" at 11575.39,891.74 h60
  text ".Layer_Name" at 577,-858.49 h60
M11 Gerber Information:
  lines w10: -292,-930.17 6308,-930.17 ; -292,-726.83 6310,-726.83 ; -292,-523.5 -292,-1133.5 3713,-1133.5 6310,-1133.5 6310,-523.5 -291.5,-523.5 -291.5,-1133.5 1284,-1133.5 ; 2173,-1133.5 2173,-523.5 ; 3440,-726.83 3440,-523.5 ; 4280,-726.83 4280,-523.5 ; 4902,-1140 4902,-937.17
  text "ALL ARTWORK VIEWED FROM TOP SIDE" at -228.5,-655.67 h60
  text "BOARD #:" at 2248,-655.67 h60
  text ".PRJ_Number" at 2793.5,-655.67 h60
  text "REV:" at 3638,-655.67 h60
  text ".PCB_Rev" at 3929.5,-655.67 h60
  text "SVN REV:" at 4476,-655.67 h60
  text ".VersionControl_RevNumber" at 4982,-655.67 h60
  text "LAYER NAME =" at -228.5,-858.49 h60
  text "TID #:" at 2248,-859 h60
  text ".TID" at 2793.5,-859 h60
  text "PLOT NAME =" at -228.5,-1064.34 h60
  text ".plot_File_Name" at 577,-1064.34 h60
  text "GENERATED    :" at 2250,-1064.34 h60
  text ".Print_Date" at 3119.5,-1064.34 h60
  text ".Print_Time" at 3848.5,-1064.34 h60
  text "TEXAS INSTRUMENTS" at 5113,-1064.34 h60
M12 Stackup:
  drawing of 399 lines, arcs and shapes, not listed
  text "Layer" at 6720.09,7770 h60
  text "Name" at 7130,7770 h60
  text "Material" at 8069.74,7770 h60
  text "Thickness" at 8929.51,7770 h60
  text "Constant" at 9579.34,7770 h60
  text "Board Layer Stack" at 10149.2,7770 h60
  text "Top Overlay" at 7130,7650 h60
  text "Top Solder" at 7130,7530 h60
  text "Solder Resist" at 8069.74,7530 h60
  text "0.50mil" at 8929.51,7530 h60
  text "3.5" at 9579.34,7530 h60
  text "1" at 6720.09,7410 h60
  text "Top Layer" at 7130,7410 h60
  text "2.80mil" at 8929.51,7410 h60
  text "Dielectric 1" at 7130,7290 h60
  text "FR-4 High Tg" at 8069.74,7290 h60
  text "7.00mil" at 8929.51,7290 h60
  text "4.2" at 9579.34,7290 h60
  text "2" at 6720.09,7170 h60
  text "Signal Layer 1" at 7130,7170 h60
  text "1.40mil" at 8929.51,7170 h60
  text "Dielectric 2" at 7130,7050 h60
  text "FR-4 High Tg" at 8069.74,7050 h60
  text "14.00mil" at 8929.51,7050 h60
  text "4.2" at 9579.34,7050 h60
  text "3" at 6720.09,6930 h60
  text "Signal Layer 2" at 7130,6930 h60
  text "1.40mil" at 8929.51,6930 h60
  text "Dielectric 4" at 7130,6810 h60
  text "FR-4 High Tg" at 8069.74,6810 h60
  text "8.20mil" at 8929.51,6810 h60
  text "4.2" at 9579.34,6810 h60
  text "4" at 6720.09,6690 h60
  text "Signal Layer 3" at 7130,6690 h60
  text "1.40mil" at 8929.51,6690 h60
  text "Dielectric 5" at 7130,6570 h60
  text "FR-4 High Tg" at 8069.74,6570 h60
  text "14.00mil" at 8929.51,6570 h60
  text "4.2" at 9579.34,6570 h60
  text "5" at 6720.09,6450 h60
  text "Signal Layer 4" at 7130,6450 h60
  text "1.40mil" at 8929.51,6450 h60
  text "Dielectric 3" at 7130,6330 h60
  text "FR-4 High Tg" at 8069.74,6330 h60
  text "7.00mil" at 8929.51,6330 h60
  text "4.2" at 9579.34,6330 h60
  text "6" at 6720.09,6210 h60
  text "Bottom Layer" at 7130,6210 h60
  text "2.80mil" at 8929.51,6210 h60
  text "Bottom Solder" at 7130,6090 h60
  text "Solder Resist" at 8069.74,6090 h60
  text "0.50mil" at 8929.51,6090 h60
  text "3.5" at 9579.34,6090 h60
  text "Bottom Overlay" at 7130,5970 h60
  text "Total board thickness:" at 6720.09,5850 h60
  text "62.40mil" at 8929.51,5850 h60
  text ".Layer_Name" at 577,-858.49 h60
M13 Component Bodies Top:
  text ".Layer_Name" at 577,-858.49 h60
M14 Component Bodies Bottom:
  text ".Layer_Name" at 577,-858.49 h60
M15 Courtyards Top:
  text ".Layer_Name" at 577,-858.49 h60
M16 Courtyards Bottom:
  text ".Layer_Name" at 577,-858.49 h60
Drill Drawing:
  circle w10: c5923.63,4030.08 r27.59
  lines w10: 5896.04,3271.23 5909.83,3271.23 5909.83,3257.43 5937.43,3257.43 5937.43,3271.23 5951.23,3271.23 5951.23,3298.82 5937.43,3298.82 5937.43,3312.62 5909.83,3312.62 5909.83,3298.82 5896.04,3298.82 5896.04,3271.23 ; 5896.04,3395.4 5909.83,3395.4 5923.63,3381.6 5937.43,3395.4 5951.23,3395.4 5937.43,3409.2 5951.23,3423 5937.43,3423 5923.63,3436.79 5909.83,3423 5896.04,3423 5909.83,3409.2 5896.04,3395.4 ; 5896.04,3560.97 5951.23,3560.97 5923.63,3505.78 5896.04,3560.97 ; 5896.04,3643.75 5909.83,3643.75 5923.63,3629.96 5937.43,3643.75 5951.23,3643.75 5937.43,3657.55 5951.23,3671.35 5937.43,3671.35 5923.63,3685.15 5909.83,3671.35 5896.04,3671.35 5909.83,3657.55 5896.04,3643.75 ; 5896.04,3781.73 5923.63,3754.13 5951.23,3781.73 5923.63,3809.32 5896.04,3781.73 ; 5896.04,3878.31 5896.04,3892.11 5909.83,3905.9 5896.04,3919.7 5896.04,3933.5 5909.83,3933.5 5923.63,3919.7 5937.43,3933.5 5951.23,3933.5 5951.23,3919.7 5937.43,3905.9 5951.23,3892.11 5951.23,3878.31 5937.43,3878.31 5923.63,3892.11 5909.83,3878.31 5896.04,3878.31 ; 5896.04,4181.85 5951.23,4181.85 5923.63,4126.66 5896.04,4181.85 ; 5907.07,3400.92 5915.35,3400.92 5923.63,3392.64 5931.91,3400.92 5940.19,3400.92 5931.91,3409.2 5940.19,3417.48 5931.91,3417.48 5923.63,3425.76 5915.35,3417.48 5907.07,3417.48 5915.35,3409.2 5907.07,3400.92 ; 5907.07,4170.81 5940.19,4170.81 5923.63,4137.7 5907.07,4170.81
  lines w12: 5846,3220.18 9001.69,3220.18 ; 5846,4213.58 9001.69,4213.58 ; 6183.72,3096 6183.72,4337.76 ; 6485.98,3096 6485.98,4337.76 ; 7077.99,3096 7077.99,4337.76 ; 7337,3096 7337,4337.76 ; 7712.04,3096 7712.04,4337.76 ; 8435.43,3096 8435.43,4337.76 ; 5846,3096 9001.69,3096 9001.69,4337.76 5846,4337.76 5846,3096
  text "Symbol" at 5920.51,4250.84 h72
  text "Count" at 6220.97,4250.84 h72
  text "Hole Size" at 6523.24,4250.84 h72
  text "Plated" at 7115.25,4250.84 h72
  text "Hole Type" at 7374.25,4250.84 h72
  text "Drill Layer Pair" at 7749.3,4250.84 h72
  text "Hole Tolerance" at 8472.68,4250.84 h72
  text "12" at 6220.97,4126.66 h60
  text "7.87mil (0.200mm)" at 6523.24,4126.66 h60
  text "PTH" at 7115.25,4126.66 h60
  text "Round" at 7374.25,4126.66 h60
  text "Top Layer - Bottom Layer" at 7749.3,4126.66 h60
  text "372" at 6220.97,4002.48 h60
  text "8.00mil (0.203mm)" at 6523.24,4002.48 h60
  text "PTH" at 7115.25,4002.48 h60
  text "Round" at 7374.25,4002.48 h60
  text "Top Layer - Bottom Layer" at 7749.3,4002.48 h60
  text "25" at 6220.97,3878.31 h60
  text "40.00mil (1.016mm)" at 6523.24,3878.31 h60
  text "PTH" at 7115.25,3878.31 h60
  text "Round" at 7374.25,3878.31 h60
  text "Top Layer - Bottom Layer" at 7749.3,3878.31 h60
  text "40" at 6220.97,3754.13 h60
  text "40.16mil (1.020mm)" at 6523.24,3754.13 h60
  text "PTH" at 7115.25,3754.13 h60
  text "Round" at 7374.25,3754.13 h60
  text "Top Layer - Bottom Layer" at 7749.3,3754.13 h60
  text "5" at 6220.97,3629.96 h60
  text "43.31mil (1.100mm)" at 6523.24,3629.96 h60
  text "PTH" at 7115.25,3629.96 h60
  text "Round" at 7374.25,3629.96 h60
  text "Top Layer - Bottom Layer" at 7749.3,3629.96 h60
  text "+/-1.97mil" at 8472.68,3629.96 h60
  text "35" at 6220.97,3505.78 h60
  text "45.28mil (1.150mm)" at 6523.24,3505.78 h60
  text "PTH" at 7115.25,3505.78 h60
  text "Round" at 7374.25,3505.78 h60
  text "Top Layer - Bottom Layer" at 7749.3,3505.78 h60
  text "4" at 6220.97,3381.6 h60
  text "125.00mil (3.175mm)" at 6523.24,3381.6 h60
  text "PTH" at 7115.25,3381.6 h60
  text "Round" at 7374.25,3381.6 h60
  text "Top Layer - Bottom Layer" at 7749.3,3381.6 h60
  text "4" at 6220.97,3257.43 h60
  text "270.00mil (6.858mm)" at 6523.24,3257.43 h60
  text "PTH" at 7115.25,3257.43 h60
  text "Round" at 7374.25,3257.43 h60
  text "Top Layer - Bottom Layer" at 7749.3,3257.43 h60
  text "497 Total" at 6220.97,3133.25 h60
  text ".Layer_Name" at 577,-858.49 h60
M17 Embedded Cavity:
  text ".Layer_Name" at 577,-858.49 h60
M18 Embedded Assembly:
  text ".Layer_Name" at 577,-858.49 h60
M19 Embedded Keepout:
  text ".Layer_Name" at 577,-858.49 h60

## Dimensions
0,-400 to 1000,-400 on M2 Board Dimensions
0,3740 to 3150,0 on M2 Board Dimensions
3150,3740 to 0,3740 on M2 Board Dimensions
